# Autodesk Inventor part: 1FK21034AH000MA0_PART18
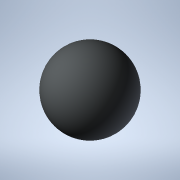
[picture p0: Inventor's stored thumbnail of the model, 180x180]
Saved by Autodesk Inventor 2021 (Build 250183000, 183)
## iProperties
Created: 2025-04
Part Number: 1FK21034AH000MA0_PART18
Material: Generic
Catalog Web Link: www.3dfindit.com
Description: -Servo synchronous motor
Document SubType Name: Modeling
Designer: psAdmin
Mass: 0.113097 g
Surface Area: 1.13097 cm^2
Volume: 0.113097 cm^3
Density: 1 g/cm^3
Appearance: PSOLRGB-212-217-219
Category: PARTsolutions
Title: 1FK21034AH000MA0_PART18
Author: Cadenas PARTsolutions
Comments: Servo synchronous motor
Sending System: PARTsolutions
Preprocessor: ST-DEVELOPER v19.3
PSOL_IDENT_0: {$CADENAS_DATA/23d-libs/siemens_ag/_cat_/ec/b7/1fk21034ah000ma0.prj},216 {VTYP=3D},{NB=1FK21034AH000
PSOL_IDENT_1: MA0_PART18},{LINA=1FK21034AH000MA0_PART18},{NN=1FK21034AH000MA0_PART18},{NOPRJ=TRUE},{DATE=19.08.202
PSOL_IDENT_2: 5 14:01:05},{GEOMDATE=30.07.2025 02:01:02},{VERSION=},{LINEID=10},{WBVAR=},{WBNUMERIC=}  {NB=1FK2103
PSOL_IDENT_3: 4AH000MA0_PART18},{LINA=1FK21034AH000MA0_PART18},{KT=DUMMY},{PREVIEW=../../../_pool_/7c/50/p_d211_xx
PSOL_IDENT_4: _00932j.png},{DESCSHORT=SIMOTICS S-1FK2 HD, SINAMICS S210 3AC 400V-480V, 1.01 Nm, 4500 rpm},{DESCLON
PSOL_IDENT_5: G=SIMOTICS S-1FK2 HD servo motor M0=1.27 Nm; PN = 0.48 kW at nN=4500 rpm (380-480 V); PN = 0.3 kW at
PSOL_IDENT_6: nN=2500 rpm (200-240 V); degree of protection IP64; cylindrical shaft D14 x 30 mm; absolute encoder
PSOL_IDENT_7: 22-bit + 12-bit multiturn (encoder AM22DQC); with OCC interface; plug size M17, rotatable; SIMOTICS
PSOL_IDENT_8: S-1FK2 servomotorfor a wide range of uses in industrial environments. SIMOTICS S‑1FK2 servomotors a
PSOL_IDENT_9: re compact synchronous motors with a high dynamic performance that set themselves apart as a result
PSOL_IDENT_10: of their high power density, degree of protection and overload capability. The motors are available
PSOL_IDENT_11: in two variants: as High Dynamic variant (highest dynamic performance as a result of the low intrins
PSOL_IDENT_12: ic moment of inertia for applications demanding a high dynamic performance with low moved masses) -
PSOL_IDENT_13: and as Compact variant (precise and stable closed-loop control for medium up to large moved masses a
PSOL_IDENT_14: s a result of a medium intrinsic moment of inertia). SIMOTICSS‑1FK2 servomotors fully exploit their
PSOL_IDENT_15: strengths in a system with the SINAMICSS210 frequency converter and simple connection using the one
PSOL_IDENT_16: cable connection (OCC). Advantages include the short control and positioning times, fast and precise
PSOL_IDENT_17: correction of disturbing quantities as well as stable control with a high dynamic performance. The
PSOL_IDENT_18: servo motors can be configured to address a wide range of requirements. For example with and without
PSOL_IDENT_19: holding brake, IP64 or IP65 degree of protection, singleturn or multiturn absolute encoders - to na
PSOL_IDENT_20: me just a few. Further, the servomotors are available in different shaft heights extending from 20 t
PSOL_IDENT_21: o 100. A shaft sealing ring is available to achieve an IP65 degree of protection and for subsequent
PSOL_IDENT_22: mounting at the motor or as spare part. SIMOTICS - the optimum motor for each and every motion contr
PSOL_IDENT_23: ol application.},{INTNO=4034106444822},{SUPPLIERALTNO=1FK2103-4AH00-0MA0},{MANUID=1FK21034AH000MA0},
PSOL_IDENT_24: {MANUNAME=Siemens},{MANUTYPEDESC=SYNCHRONOUS MOTOR 1FK2 HD 1,27 NM},{AAU732=SIMOTICS},{AAO057=S-1FK2
PSOL_IDENT_25: },{AAU734=SIMOTICS S-1FK2 HD servo motor M0=1.27 Nm; PN = 0.48 kW at nN=4500 rpm (380-480 V); PN = 0
PSOL_IDENT_26: .3 kW at nN=2500 rpm (200-240 V); degree of protection IP64; cylindrical shaft D14 x 30 mm; absolute
PSOL_IDENT_27: encoder 22-bit + 12-bit multiturn (encoder AM22DQC); with OCC interface; plug size M17, rotatable;}
PSOL_IDENT_28: ,{AAW338=SYNCHRONOUS MOTOR 1FK2 HD 1,27 NM},{AAO742=SIMOTICS},{AAO663=4034106444822},{NOCUPEROU=1},{
PSOL_IDENT_29: PRICEQUANTITY=1},{QUANTITYMIN=1},{QUANTITYINT=1},{CTN=85015100},{COO=RO},{AAO676=1FK2103-4AH00-0MA0}
PSOL_IDENT_30: ,{AAO677=Siemens AG},{ORDERUNIT=C62},{CONTENTUNIT=C62}
NB: 1FK21034AH000MA0_PART18
NT: Servo synchronous motor
NBSYN: $MANUID._PART18
LINA: 1FK21034AH000MA0_PART18
CATALOG: SIEMENS
PREVIEW: ../../../_pool_/7c/50/p_d211_xx_00932j.png
DESCSHORT: SIMOTICS S-1FK2 HD, SINAMICS S210 3AC 400V-480V, 1.01 Nm, 4500 rpm
DESCLONG: SIMOTICS S-1FK2 HD servo motor M0=1.27 Nm; PN = 0.48 kW at nN=4500 rpm (380-480 V); PN = 0.3 kW at nN=2500 rpm (200-240 V); degree of protection IP64; cylindric
INTNO: 4034106444822
SUPPLIERALTNO: 1FK2103-4AH00-0MA0
MANUID: 1FK21034AH000MA0
MANUNAME: Siemens
MANUTYPEDESC: SYNCHRONOUS MOTOR 1FK2 HD 1,27 NM
AAU732: SIMOTICS
AAO057: S-1FK2
AAU734: SIMOTICS S-1FK2 HD servo motor M0=1.27 Nm; PN = 0.48 kW at nN=4500 rpm (380-480 V); PN = 0.3 kW at nN=2500 rpm (200-240 V); degree of protection IP64; cylindric
AAW338: SYNCHRONOUS MOTOR 1FK2 HD 1,27 NM
AAO742: SIMOTICS
AAO663: 4034106444822.0
NOCUPEROU: 1
PRICEQUANTITY: 1
QUANTITYMIN: 1
QUANTITYINT: 1
CTN: 85015100
COO: RO
ARTICLENO: 1FK21034AH000MA0_PART18
BOMINFO: 1FK21034AH000MA0_PART18
CREATOR: CADENAS GmbH
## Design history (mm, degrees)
feature "2025_04_17_15_01_37_0314"
body "Solid1"
